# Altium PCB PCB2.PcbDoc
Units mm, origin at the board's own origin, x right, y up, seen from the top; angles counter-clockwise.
Board outline 45.97 x 46.48 mm, 2 copper layers (Top Layer, Bottom Layer); 13 components, 15 nets, 50 pads, 2 vias.
Unrouted connection lines stored in the file: 1.
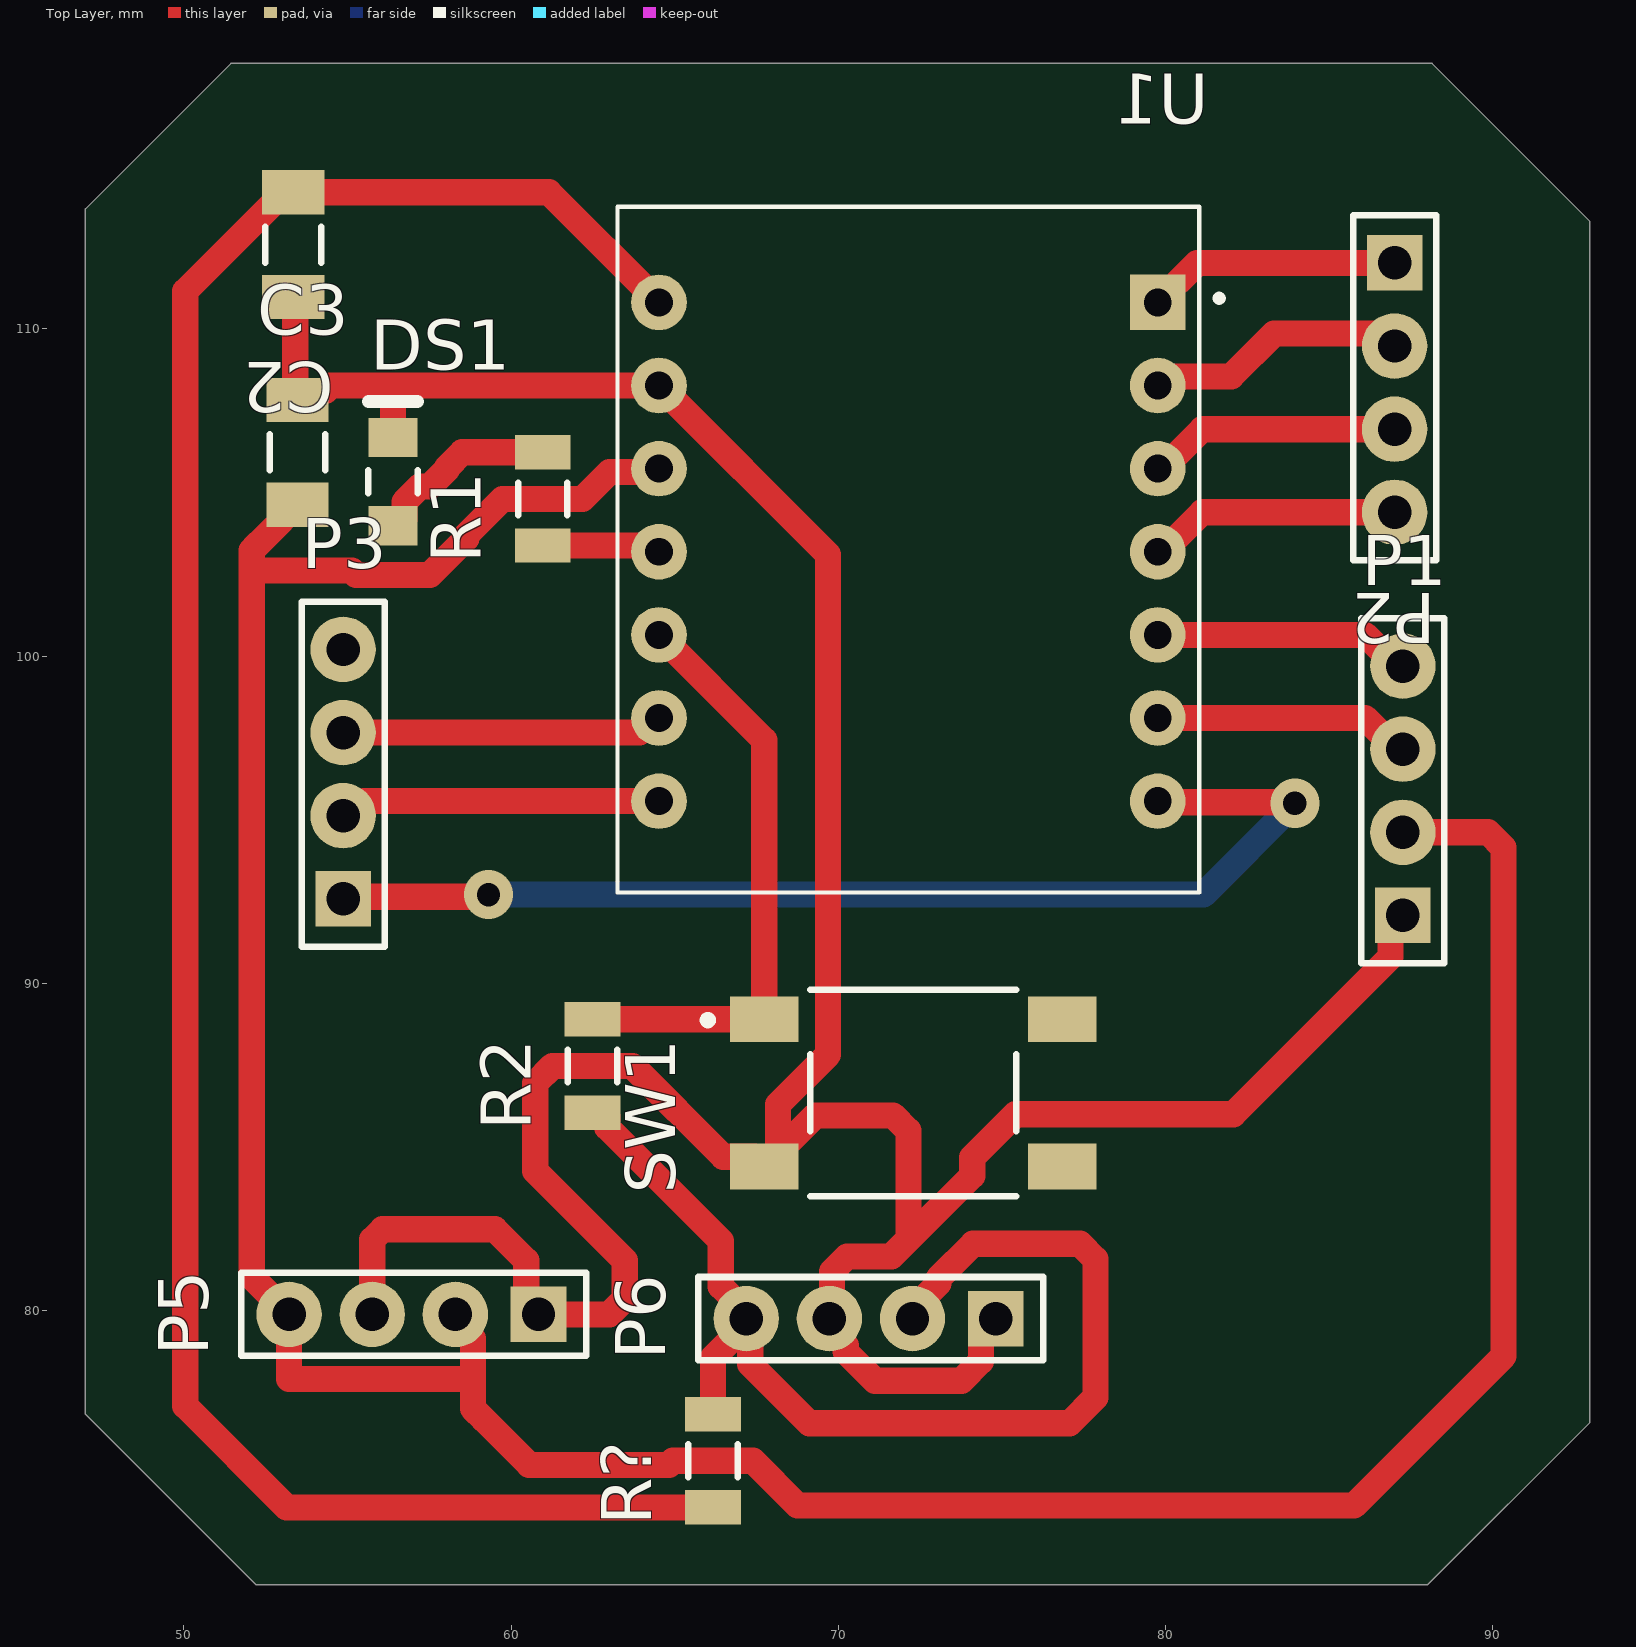
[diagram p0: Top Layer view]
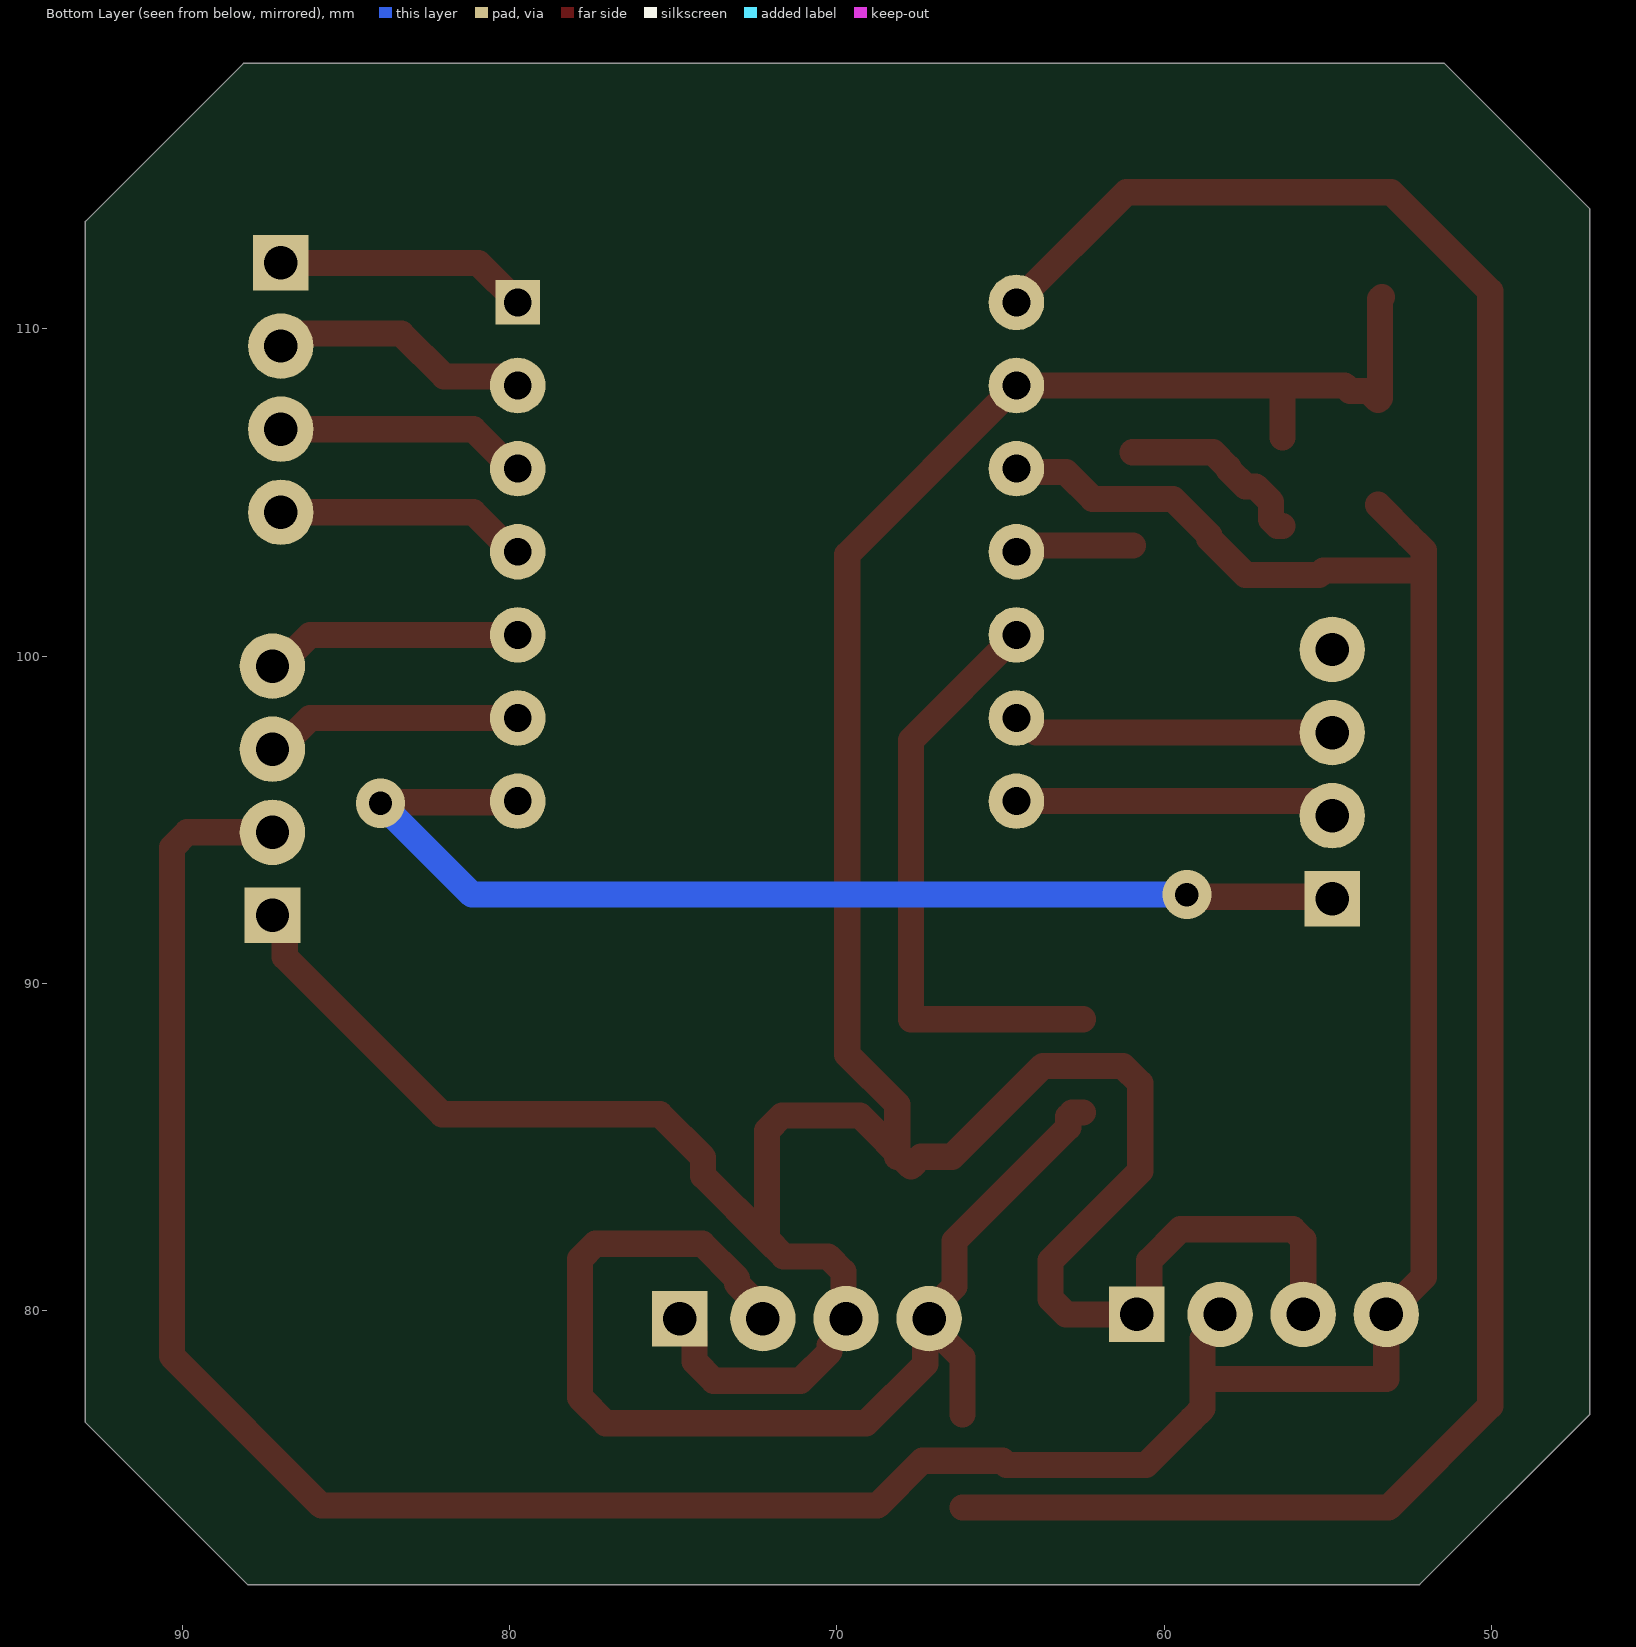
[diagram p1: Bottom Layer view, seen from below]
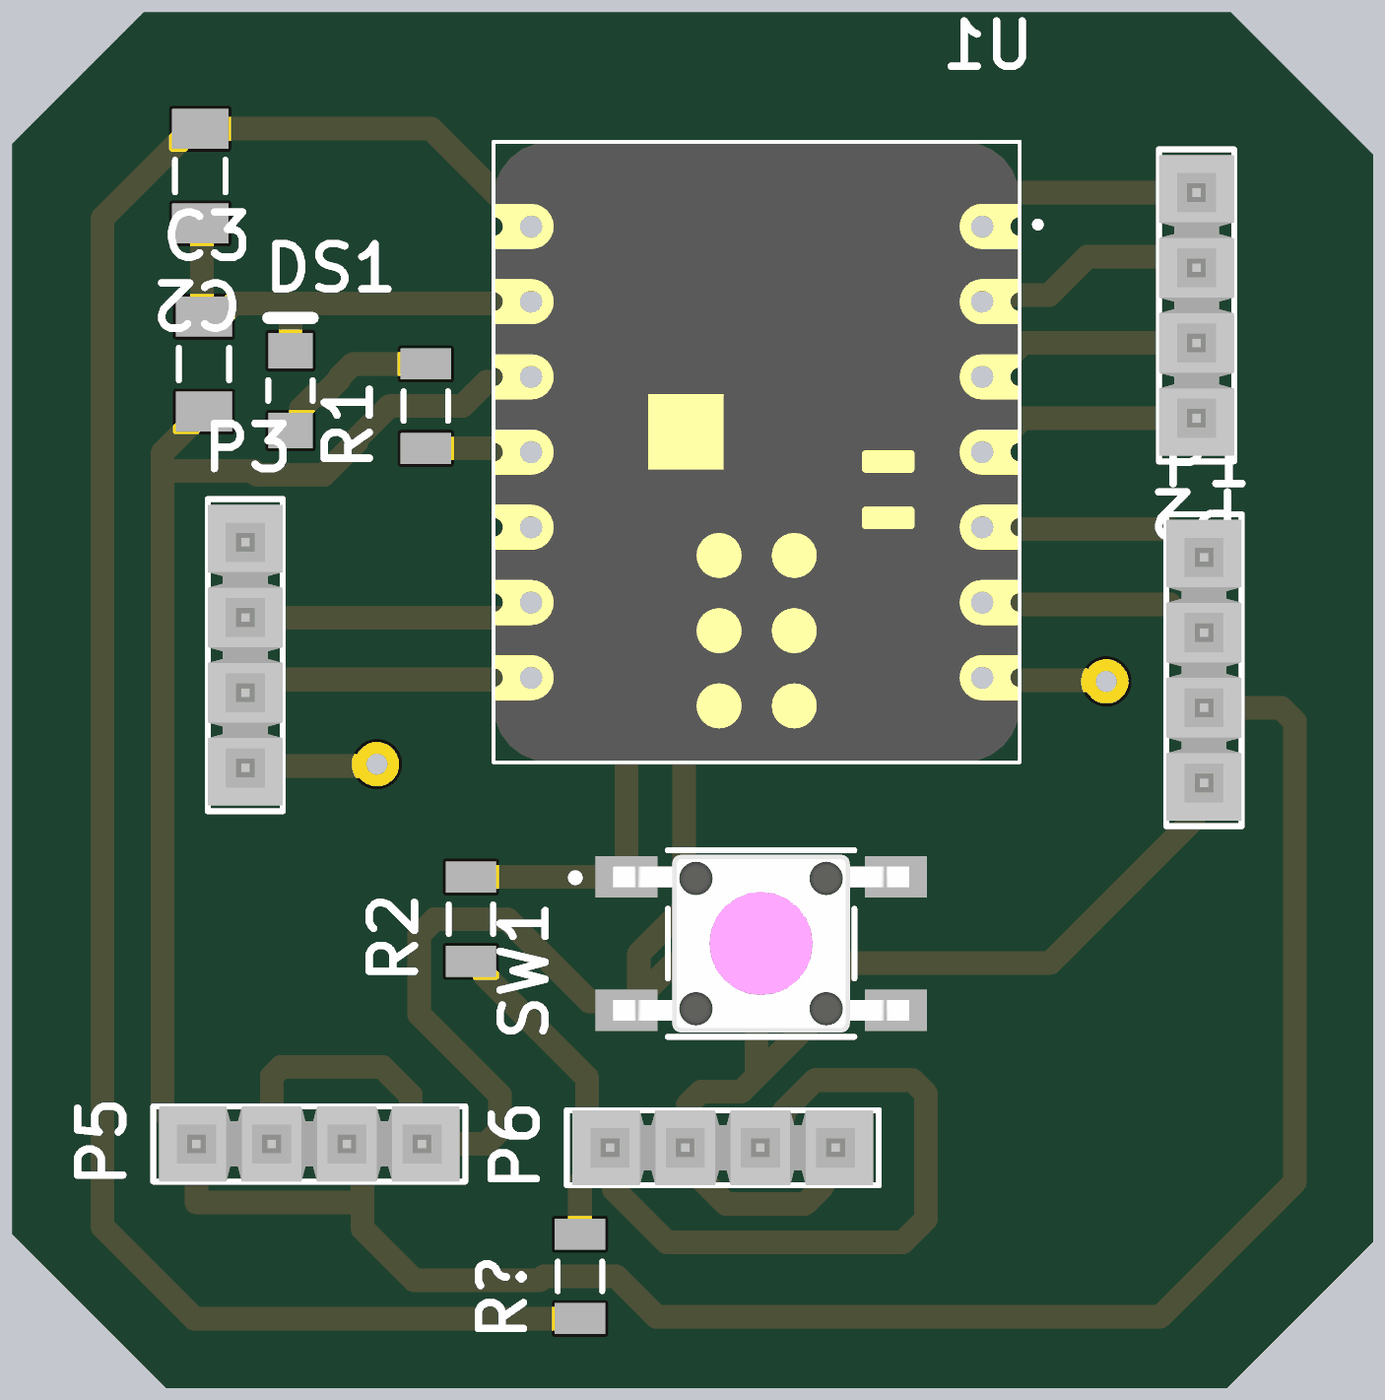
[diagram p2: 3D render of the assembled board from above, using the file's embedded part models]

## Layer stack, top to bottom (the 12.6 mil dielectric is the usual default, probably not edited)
Top Solder: solder mask 0.0102, Solder Resist, Dk 3.5
Top Layer: signal copper 0.0356
Dielectric 1: dielectric 0.32, FR-4, Dk 4.8
Bottom Layer: signal copper 0.0356
Bottom Solder: solder mask 0.0102, Solder Resist, Dk 3.5

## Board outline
46.99,76.835 46.99,113.665 51.435,118.11 88.138,118.11 92.964,113.284 92.964,76.581 88.011,71.628 52.197,71.628

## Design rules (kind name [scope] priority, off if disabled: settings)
Clearance [All] p1: gap=0.5 ignorepadtopadclearanceinfootprint=FALSE
PolygonConnect [All] p1: connectstyle=Relief reliefconductorwidth=0.254 reliefentries=4 polygonreliefangle="90 Angle" airgapwidth=0.254
RoutingVias [All] p1: holewidth=0.711 width=1.27 viastyle="Through Hole" minholewidth=0.711 minwidth=1.27 maxholewidth=0.711 maxwidth=1.27
SolderMaskExpansion [All] p1: expansion=0.102 istentingtop=FALSE
SupplyNets "Schematic Supply Nets_3" [InNet('+3.3')] p1: voltage=0.000
SupplyNets "Schematic Supply Nets_2" [InNet('+5')] p2: voltage=0.000
SupplyNets "Schematic Supply Nets_1" [InNet('GND')] p3: voltage=0.000
Width [All] p1: maxlimit=0.8 minlimit=0.8 preferedwidth=0.8 minimp=50.000000 maximp=50.000000 favimp=50.000000
30 further rules are at their usual default settings.

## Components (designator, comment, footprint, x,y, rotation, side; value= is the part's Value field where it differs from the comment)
C2 "CAP 22pF 50V 1206(3216)" CAPC1206(3216)100_M 53.34,112.573 r270 top value=22pF
C3 "CAP 22pF 50V 1206(3216)" CAPC1206(3216)100_M 53.467,106.223 r90 top value=22pF
DS1 "SML-LX1206IC-TR" LUMX-SML-LX1206IC_V 56.388,105.33 r90 top
P1 "TSW-104-08-F-S" SMTC-TSW-104-08-X-S 87.249,92.075 r90 top
P2 "TSW-104-08-F-S" SMTC-TSW-104-08-X-S 86.995,112.014 r270 top
P3 "TSW-104-08-F-S" SMTC-TSW-104-08-X-S 54.864,92.583 r90 top
P5 "TSW-104-08-F-S" SMTC-TSW-104-08-X-S 60.833,79.883 r180 top
P6 "TSW-104-08-F-S" SMTC-TSW-104-08-X-S 74.803,79.756 r180 top
R1 "" RESC3116X65X40NL10T20 60.96,104.803 r90 top
R2 "RC1206FR-076R98L" RESC3116X65X40NL10T20 62.484,87.475 r90 top
R? "RC1206FR-076R98L" RESC3116X65X40NL10T20 66.167,75.41 r90 top
SW1 "1-1977223-9" FP-1-1977223-9-MFG 72.285,86.65 r90 top
U1 "XIAO_ESP32C3" MODULE_XIAO_ESP32C3 72.136,103.251 r180 top

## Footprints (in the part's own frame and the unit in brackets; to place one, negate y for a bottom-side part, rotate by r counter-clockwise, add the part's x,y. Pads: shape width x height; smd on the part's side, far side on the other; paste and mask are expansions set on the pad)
CAPC1206(3216)100_M [mm] "Chip Capacitor, Body 3.2x1.6mm, Height 1mm, IPC Low Density"
  rect 1.35x1.9 smd: 1(-1.6,0) 2(1.6,0)
  silkscreen extent -0.55,-0.85 0.55,0.85, body extent -1.7,-0.9 1.7,0.9, height 1
FP-1-1977223-9-MFG [mm]
  rect 1.4x2.1 smd paste+0 mask+0: 1(2.25,4.55) 2(2.25,-4.55) 3(-2.25,4.55) 4(-2.25,-4.55)
  silkscreen extent -3.15,-3.15 3.15,6.4, body extent -3.25,-5.7 3.25,5.7, height 0.25
LUMX-SML-LX1206IC_V [mm] "SMD, 2-Leads, Body 3.2x1.5mm"
  rect 1.2x1.5 smd: 1(-1.35,0) 2(1.35,0)
  silkscreen extent -0.35,-0.75 2.45,0.75, body extent -1.6,-0.8 1.6,0.8, height 1.1
MODULE_XIAO_ESP32C3 [mm]
  rect 1.7x1.7 / inner round 1.358 / far side rect 1.358x1.358 hole 0.85 mask+0.102: 1(-7.62,-7.557)
  round 1.7 hole 0.85 mask+0.102: 2(-7.62,-5.017) 3(-7.62,-2.477) 4(-7.62,0.063) 5(-7.62,2.603) 6(-7.62,5.143) 7(-7.62,7.683) 8(7.62,7.684) 9(7.62,5.144) 10(7.62,2.604) 11(7.62,0.064) 12(7.62,-2.476) 13(7.62,-5.016) 14(7.62,-7.556)
  silkscreen extent -9.6,-10.48 8.89,10.48, body extent -8.89,-11.99 8.89,10.48, height 0
RESC3116X65X40NL10T20 [mm] "Chip Resistor, 2-Leads, Body 3.10x1.60mm, IPC Medium Density"
  rect 1.05x1.7 smd: 1(-1.425,0) 2(1.425,0)
  silkscreen extent -0.5,-0.75 0.5,0.75, body extent -1.6,-0.85 1.6,0.85, height 0.65
SMTC-TSW-104-08-X-S [mm] ".025 SQ Post Terminal Strip Assembly, 1x4 Pins, Vertical, 2.54mm Pitch, Male"
  rect 1.7x1.7 hole 1.02: 1(0,0)
  round 2 hole 1.02: 2(2.54,0) 3(5.08,0) 4(7.62,0)
  silkscreen extent -1.46,-1.27 9.08,1.27, body extent -1.27,-1.27 8.89,1.27, height 8.38

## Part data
C2 C3: library part CMP-1037-00980-1, "CAP 22pF 50V ±10% 1206 (3216 Metric) Thickness 1mm SMD", Case-EIA=1206, Case-Metric=3216, Rated Voltage="50 V", Tolerance=Â±10%
DS1: library part CMP-2000-07123-1, "LED Red, 65 mW, -40 to 85 degC, 2-Pin SMD, RoHS, Tape and Reel", Color=Red, Manufacturer=Lumex, Operating Temperature=-25to85C, Package Description="2-Pin Surface Mount Device, Body 3.2 x 1.5 mm", Package Reference=SML-LX1206IC, Reverse Voltage=5(Min)V, Supplier_Package=SMD
P1 P2 P3 P5 P6: library part CMP-1024-00355-1, "0.025\" SQ Post Header, Through-hole, Vertical, -55 to 125 degC, 2.54 mm Pitch, 4-Pin, Male, RoHS", Manufacturer=Samtec, Temperature Range="-55 to 125 degC"
R1: library part CMP-2003-03854-1, Manufacturer=Yageo, Part Number=RC1206FR-076R98L
R2 R?: library part CMP-2003-03854-1, Manufacturer=Yageo
SW1: library part CMP-03407-000015-1, "SWITCH TACTILE SPST-NO 0.05A 24V", Actuator Color=Pink, Case/Package=SMD/SMT, Current Rating=50mA, Max Operating Temperature=105°C, Max Voltage Rating (DC)=24V, Min Operating Temperature=-40°C, Operating Force=2.55N, Package Quantity=750
U1: "Dev.kit: evaluation; u.FL antenna,prototype board; XIAO; PIN: 2x7", Package=None

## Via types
v1: diameter 1.5, hole 0.711, Top Layer to Bottom Layer, 2 vias

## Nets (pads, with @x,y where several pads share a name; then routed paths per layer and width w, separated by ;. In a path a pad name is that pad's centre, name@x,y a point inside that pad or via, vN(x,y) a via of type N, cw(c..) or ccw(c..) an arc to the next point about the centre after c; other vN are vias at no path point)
+3.3: C3.1 P1.2 P5.2 P5.4 U1.12 | length 103.8
  Top Layer w0.8: 52.07,102.155 52.07,81.026 P5.4 53.213,77.914 58.766,77.914 58.829,77.851 ; 52.07,102.235 52.07,102.616 ; 52.07,103.229 52.07,102.616 ; 52.127,103.286 52.538,103.697 52.539,103.695 C3.1 ; P5.2 58.293,79.68 58.829,79.144 58.829,77.851 ; U1.12 64.409,105.621 63.001,105.621 62.183,104.803 59.737,104.803 58.624,103.69 58.624,103.593 57.511,102.48 55.265,102.48 55.129,102.616 52.07,102.616 ; P1.2 89.852,94.615 90.321,94.146 90.321,78.608 85.754,74.041 68.759,74.041 67.39,75.41 64.944,75.41 64.819,75.285 60.551,75.285 59.158,76.678 58.829,77.007 58.829,77.851
+5: C2.1 P6.2 P6.4 R2.1 R?.1 R?.2 U1.14 | length 104.6
  Top Layer w0.8: R2.1 62.809,86.05 62.934,85.925 62.934,85.6 66.403,82.131 66.403,80.739 67.183,79.959 P6.4 ; U1.14 61.151,114.173 C2.1 53.065,114.173 50.038,111.146 50.038,77.089 53.142,73.985 R?.1 ; R?.2 66.167,78.56 67.183,79.576 P6.4 ; P6.2 72.263,80.035 73.053,80.825 73.053,80.979 74.116,82.042 77.382,82.042 77.851,81.573 77.851,77.343 77.064,76.556 69.113,76.556 67.304,78.365 67.304,79.635 P6.4
A0: P2.1 U1.1 | length 7.7
  Top Layer w0.8: U1.1 80.962,112.014 P2.1
A1: P2.2 U1.2 | length 8.1
  Top Layer w0.8: U1.2 79.907,108.267 80.186,108.546 82.003,108.546 83.312,109.855 86.411,109.855 86.792,109.474 P2.2
A2: P2.3 U1.3 | length 7.7
  Top Layer w0.8: U1.3 79.907,105.727 81.113,106.934 P2.3
BOTON: R2.2 SW1.1 U1.10 | length 18.3
  Top Layer w0.8: R2.2 SW1.1 67.735,97.429 U1.10
D3: P2.4 U1.4 | length 7.7
  Top Layer w0.8: U1.4 79.907,103.188 81.113,104.394 P2.4
D6: P3.1 U1.7 | length 34.5
  Top Layer w0.8: P3.1 54.927,92.647 59.245,92.647 v1(59.309,92.71) ; U1.7 79.788,95.536 83.915,95.536 v1(83.947,95.504)
  Bottom Layer w0.8: v1(59.309,92.71) 81.153,92.71 v1(83.947,95.504)
D7: P3.2 U1.8 | length 9.8
  Top Layer w0.8: P3.2 55.067,95.123 55.511,95.567 U1.8
D8: P3.3 U1.9 | length 9.8
  Top Layer w0.8: P3.3 63.921,97.663 64.365,98.108 U1.9
GND: C2.2 C3.2 DS1.2 P1.1 P5.1 P5.3 P6.1 P6.3 SW1.3 U1.13 | length 111.1
  Top Layer w0.8: C2.2 53.404,110.909 53.404,107.886 C3.2 53.742,108.098 54.316,108.098 54.486,108.267 56.388,108.267 ; P5.3 55.753,82.169 56.07,82.486 59.499,82.486 60.458,81.528 60.458,80.258 P5.1 63.002,79.883 63.471,80.352 63.471,81.528 60.734,84.265 60.734,86.948 61.261,87.475 63.707,87.475 66.482,84.7 67.435,84.7 SW1.3 69.3,85.965 71.669,85.965 72.137,85.497 72.137,82.17 ; DS1.2 56.388,108.267 ; 58.125,108.267 56.388,108.267 ; 58.205,108.267 U1.13 69.685,103.099 69.685,87.827 68.158,86.3 SW1.3@68.158,84.7 ; P6.3 69.803,79.836 69.803,81.187 70.272,81.656 71.623,81.656 72.137,82.17 ; P6.3@69.723,79.903 69.723,79.431 70.225,78.93 70.225,78.746 71.115,77.856 73.762,77.856 74.353,78.447 74.353,79.306 P6.1 ; P1.1 86.874,91.7 86.874,90.811 82.063,86 75.412,86 74.09,84.677 74.09,84.123 72.137,82.17
LED: R1.1 U1.11 | length 3.6
  Top Layer w0.8: R1.1 64.175,103.378 64.365,103.188 U1.11
NetDS1_1: DS1.1 R1.2 | length 5.8
  Top Layer w0.8: DS1.1 56.538,103.98 56.738,104.18 56.738,104.711 57.207,105.18 57.511,105.18 58.038,105.707 58.038,105.759 58.507,106.228 R1.2
SCL: P1.3 U1.6 | length 7.9
  Top Layer w0.8: U1.6 86.094,98.108 87.046,97.155 P1.3
SDA: P1.4 U1.5 | length 7.9
  Top Layer w0.8: U1.5 86.094,100.647 87.046,99.695 P1.4
pads on no net: P3.4 SW1.2 SW1.4

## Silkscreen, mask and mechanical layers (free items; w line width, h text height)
Mechanical 1:
  the board outline again, w1.5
